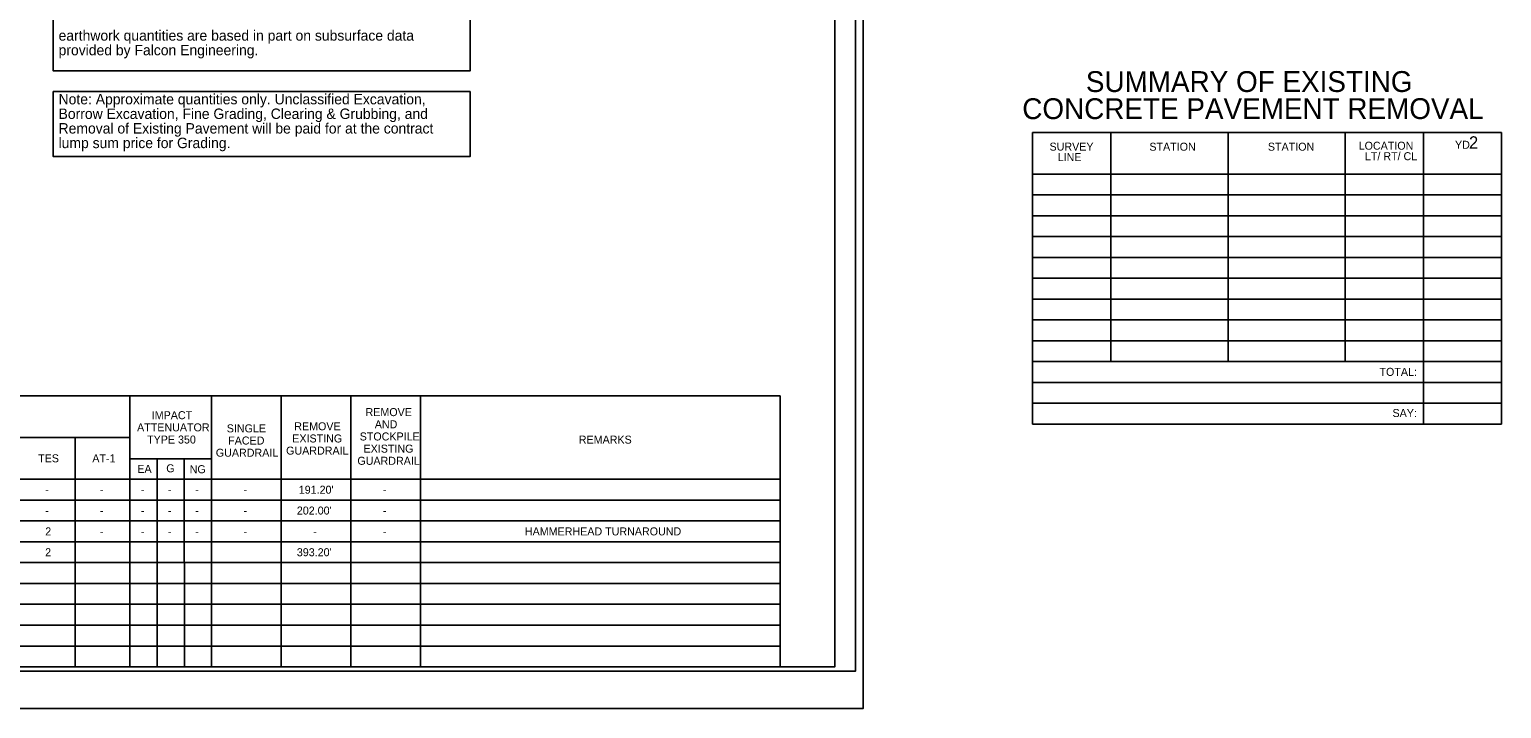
# Model space of a CAD drawing. Extents: x 1729984.8 to 1730033.5, y 539934.2 to 539956.2.
# Drawn here: x 1730015.88 to 1730033.54, y 539934.17 to 539942.32 of the extents above; entities that cross this region are included whole.
import ezdxf

# ---------------------------------------------------------------- set-up
doc = ezdxf.new("R2010")
doc.units = 0
for name, color, linetype in [('Sheet Cutting Line CELL', 7, 'Continuous'), ('Sheet Plot Border Inside CELL', 7, 'Continuous'), ('Sheet Plot Border Outside CELL', 7, 'Continuous'), ('Sheet Summary Combination CELL', 7, 'Continuous'), ('Sheet Summary Combination Grid CELL', 7, 'Continuous'), ('Sheet Summary Earthwork CELL', 7, 'Continuous')]:
    doc.layers.add(name, color=color, linetype=linetype)

msp = doc.modelspace()

# ---------------------------------------------------------------- linework, layer by layer
at = {"layer": 'Sheet Cutting Line CELL'}
msp.add_line((1729992.203, 539934.171), (1730025.883, 539934.171), dxfattribs=at)
at = {"layer": 'Sheet Plot Border Inside CELL'}
msp.add_lwpolyline([(1730025.793, 539955.722), (1729992.463, 539955.722), (1729992.463, 539934.62), (1730025.793, 539934.62)], close=True, dxfattribs=at)
at = {"layer": 'Sheet Plot Border Outside CELL'}
msp.add_lwpolyline([(1730025.883, 539956.171), (1729992.203, 539956.171), (1729992.203, 539934.171), (1730025.883, 539934.171)], close=True, dxfattribs=at)
at = {"layer": 'Sheet Summary Combination CELL'}
for p, q in [((1730030.742, 539941.082), (1730030.742, 539941.082)), ((1730030.867, 539941.08), (1730030.867, 539941.08)), ((1730031.048, 539941.084), (1730031.048, 539941.084)), ((1730031.16, 539941.082), (1730031.16, 539941.082))]:
    msp.add_line(p, q, dxfattribs=at)
msp.add_lwpolyline([(1730025.543, 539955.671), (1729995.543, 539955.671), (1729995.543, 539934.671), (1730025.543, 539934.671)], close=True, dxfattribs=at)
at = {"layer": 'Sheet Summary Combination Grid CELL'}
for p, q in [((1730027.917, 539941.083), (1730033.544, 539941.083)), ((1730027.917, 539941.083), (1730027.917, 539937.583)), ((1730028.855, 539941.083), (1730028.855, 539938.333)), ((1730030.262, 539941.083), (1730030.262, 539938.333)), ((1730031.668, 539941.083), (1730031.668, 539938.333)), ((1730032.606, 539941.083), (1730032.606, 539937.583)), ((1730033.544, 539941.083), (1730033.544, 539937.583)), ((1730027.917, 539940.583), (1730033.544, 539940.583)), ((1730027.917, 539940.333), (1730033.544, 539940.333)), ((1730027.917, 539940.083), (1730033.544, 539940.083)), ((1730027.917, 539939.833), (1730033.544, 539939.833)), ((1730027.917, 539939.583), (1730033.544, 539939.583)), ((1730027.917, 539939.333), (1730033.544, 539939.333)), ((1730027.917, 539939.083), (1730033.544, 539939.083)), ((1730027.917, 539938.833), (1730033.544, 539938.833)), ((1730027.917, 539938.583), (1730033.544, 539938.583)), ((1730027.917, 539938.333), (1730033.544, 539938.333)), ((1730027.917, 539938.083), (1730033.544, 539938.083)), ((1729996.199, 539937.921), (1730024.887, 539937.921)), ((1730017.086, 539937.921), (1730017.086, 539934.671)), ((1730018.063, 539937.921), (1730018.063, 539934.671)), ((1730018.899, 539937.921), (1730018.899, 539934.671)), ((1730019.735, 539937.921), (1730019.735, 539934.671)), ((1730020.572, 539937.921), (1730020.572, 539934.671)), ((1730024.887, 539937.921), (1730024.887, 539934.671)), ((1730027.917, 539937.833), (1730033.544, 539937.833)), ((1730027.917, 539937.583), (1730033.544, 539937.583)), ((1730017.086, 539937.421), (1730008.855, 539937.421)), ((1730016.429, 539937.421), (1730016.429, 539934.671)), ((1730017.086, 539937.166), (1730018.058, 539937.166)), ((1730017.411, 539937.166), (1730017.412, 539934.671)), ((1730017.738, 539937.166), (1730017.739, 539934.671)), ((1729996.199, 539936.921), (1730017.086, 539936.921)), ((1730017.086, 539936.921), (1730024.887, 539936.921)), ((1729996.199, 539936.671), (1730017.086, 539936.671)), ((1730017.086, 539936.671), (1730024.887, 539936.671)), ((1729996.199, 539936.421), (1730017.086, 539936.421)), ((1730017.086, 539936.421), (1730024.887, 539936.421)), ((1729996.199, 539936.171), (1730017.086, 539936.171)), ((1730017.086, 539936.171), (1730024.887, 539936.171)), ((1729996.199, 539935.921), (1730017.086, 539935.921)), ((1730017.086, 539935.921), (1730024.887, 539935.921)), ((1729996.199, 539935.671), (1730017.086, 539935.671)), ((1730017.086, 539935.671), (1730024.887, 539935.671)), ((1729996.199, 539935.421), (1730017.086, 539935.421)), ((1730017.086, 539935.421), (1730024.887, 539935.421)), ((1729996.199, 539935.171), (1730017.086, 539935.171)), ((1730017.086, 539935.171), (1730024.887, 539935.171)), ((1729996.199, 539934.921), (1730017.086, 539934.921)), ((1730017.086, 539934.921), (1730024.887, 539934.921)), ((1729995.543, 539934.671), (1730025.543, 539934.671))]:
    msp.add_line(p, q, dxfattribs=at)
at = {"layer": 'Sheet Summary Earthwork CELL'}
for points in [[(1730016.167, 539942.6), (1730021.168, 539942.6), (1730021.168, 539941.82), (1730016.167, 539941.82)], [(1730016.167, 539941.573), (1730021.168, 539941.573), (1730021.168, 539940.793), (1730016.167, 539940.793)]]:
    msp.add_lwpolyline(points, close=True, dxfattribs=at)

# ---------------------------------------------------------------- texts
at = {"layer": 'Sheet Summary Combination CELL'}
for s, p in [('SUMMARY OF EXISTING', (1730028.556, 539941.567)), ('CONCRETE PAVEMENT REMOVAL', (1730027.793, 539941.242))]:
    msp.add_text(s, height=0.25, rotation=0.0119, dxfattribs=at).set_placement(p)
for s, p in [('SURVEY', (1730028.12, 539940.864)), ('STATION', (1730029.318, 539940.863)), ('STATION', (1730030.74, 539940.863)), ('LOCATION', (1730031.829, 539940.875)), ('LINE', (1730028.218, 539940.738)), ('LT/ RT/ CL', (1730031.904, 539940.749)), ('TOTAL:', (1730032.079, 539938.162)), ('REMOVE', (1730019.913, 539937.679)), ('SAY:', (1730032.235, 539937.668)), ('ATTENUATOR', (1730017.172, 539937.496)), ('IMPACT', (1730017.348, 539937.642)), ('SINGLE', (1730018.248, 539937.484)), ('REMOVE', (1730019.058, 539937.509)), ('AND', (1730020.024, 539937.533)), ('TYPE 350', (1730017.292, 539937.35)), ('FACED', (1730018.265, 539937.338)), ('EXISTING', (1730019.034, 539937.363)), ('STOCKPILE', (1730019.843, 539937.387)), ('REMARKS', (1730022.472, 539937.349)), ('GUARDRAIL', (1730018.117, 539937.192)), ('GUARDRAIL', (1730018.96, 539937.217)), ('EXISTING', (1730019.889, 539937.241)), ('TES', (1730015.985, 539937.125)), ('AT-1', (1730016.635, 539937.124)), ('EA', (1730017.175, 539936.998)), ('G', (1730017.522, 539937.005)), ('NG', (1730017.803, 539936.994)), ('GUARDRAIL', (1730019.815, 539937.095)), ('-', (1730016.07, 539936.748)), ('-', (1730016.725, 539936.748)), ('-', (1730017.217, 539936.748)), ('-', (1730017.543, 539936.748)), ('-', (1730017.869, 539936.748)), ('-', (1730018.449, 539936.748)), ("191.20'", (1730019.112, 539936.748)), ('-', (1730020.122, 539936.748)), ('-', (1730016.07, 539936.498)), ('-', (1730016.725, 539936.498)), ('-', (1730017.217, 539936.498)), ('-', (1730017.543, 539936.498)), ('-', (1730017.869, 539936.498)), ('-', (1730018.449, 539936.498)), ("202.00'", (1730019.089, 539936.498)), ('-', (1730020.122, 539936.498)), ('2', (1730016.07, 539936.248)), ('HAMMERHEAD TURNAROUND', (1730021.825, 539936.248)), ('-', (1730016.725, 539936.248)), ('-', (1730017.217, 539936.248)), ('-', (1730017.543, 539936.248)), ('-', (1730017.869, 539936.248)), ('-', (1730018.449, 539936.248)), ('-', (1730019.285, 539936.248)), ('-', (1730020.122, 539936.248)), ('2', (1730016.069, 539935.998)), ("393.20'", (1730019.089, 539935.998))]:
    msp.add_text(s, height=0.096, dxfattribs=at).set_placement(p)
at = {"layer": 'Sheet Summary Combination Grid CELL'}
for s, height, p in [('YD', 0.096, (1730032.985, 539940.886)), ('2', 0.15, (1730033.152, 539940.886))]:
    msp.add_text(s, height=height, dxfattribs=at).set_placement(p)
at = {"layer": 'Sheet Summary Earthwork CELL'}
for s, p in [('earthwork quantities are based in part on subsurface data', (1730016.23, 539942.183)), ('provided by Falcon Engineering.', (1730016.23, 539942.008)), ('Note: Approximate quantities only. Unclassified Excavation,', (1730016.23, 539941.419)), ('Borrow Excavation, Fine Grading, Clearing & Grubbing, and', (1730016.23, 539941.244)), ('Removal of Existing Pavement will be paid for at the contract', (1730016.23, 539941.069)), ('lump sum price for Grading.', (1730016.23, 539940.894))]:
    msp.add_text(s, height=0.125, dxfattribs=at).set_placement(p)

doc.saveas('drawing.dxf')
